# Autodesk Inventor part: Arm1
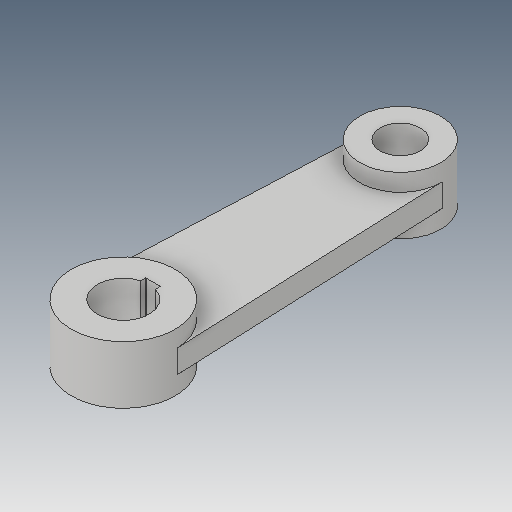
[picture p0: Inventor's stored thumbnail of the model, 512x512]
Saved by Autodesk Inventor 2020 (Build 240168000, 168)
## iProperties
Created: 2016-05
Part Number: Arm1
Material: Generic
Document SubType Name: Modeling
Designer: CADCIM
Density: 1 g/cm^3
Appearance: Default
Author: CADCIM
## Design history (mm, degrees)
sketch "Sketch1"
  geometry: C1 r 56.25 at (0, 0); C2 r 28 at (0, 0); C3 r 43.75 at (0, -300); C4 r 21.75 at (0, -300); 1 further point
  constraints: 4 centre point, 3 coincident
  dimensions: "d0" = 112.5 diameter of C1; "d1" = 56 diameter of C2; "d2" = 87.5 diameter of C3; "d3" = 43.5 diameter of C4; "d4" = 300 distance of C4.centre C2.centre
extrude "Extrusion1" new body sketch "Sketch1" stored distance "d5" = 62.5; taper "d6" = 0 deg
sketch "Sketch2"
  geometry: L1 (56.201, -2.344)-(43.712, -301.823); L2 (-56.201, -2.344)-(-43.712, -301.823); A1 r 56.25 centre (0, 0) between (-56.201, -2.344) and (56.201, -2.344); A2 r 43.75 centre (0, -300) between (43.712, -301.823) and (-43.712, -301.823); 3 further points
  constraints: 4 end point, 4 point on circle, 2 centre point, 2 coincident
extrude "Extrusion2" join sketch "Sketch2" stored distance "d7" = 25; taper "d8" = 0 deg
sketch "Sketch3"
  geometry: L1 (0, 0)-(0, 99.622); L2 (-8, 26.833)-(8, 26.833); L3 (8, 26.833)-(8, 32.3); L4 (8, 32.3)-(-8, 32.3); L5 (-8, 32.3)-(-8, 26.833); L6 (0, 0)-(0, -28); A1 r 28 centre (0, 0) between (-8, 26.833) and (8, 26.833) reference
  constraints: 12 end point, 3 point on circle, 2 parallel, 2 vertical, 1 horizontal, 1 perpendicular, 1 other
  dimensions: "d10" = 16 distance of L3.end L4.end; "d11" = 60.3 distance from line of L4 L6.end
extrude "Extrusion3" cut sketch "Sketch3" extent not by distance; stored distance "d12" = 25; taper "d13" = 0 deg
fillet "Fillet1" dims "d14" = 0.4
body "Solid1"
